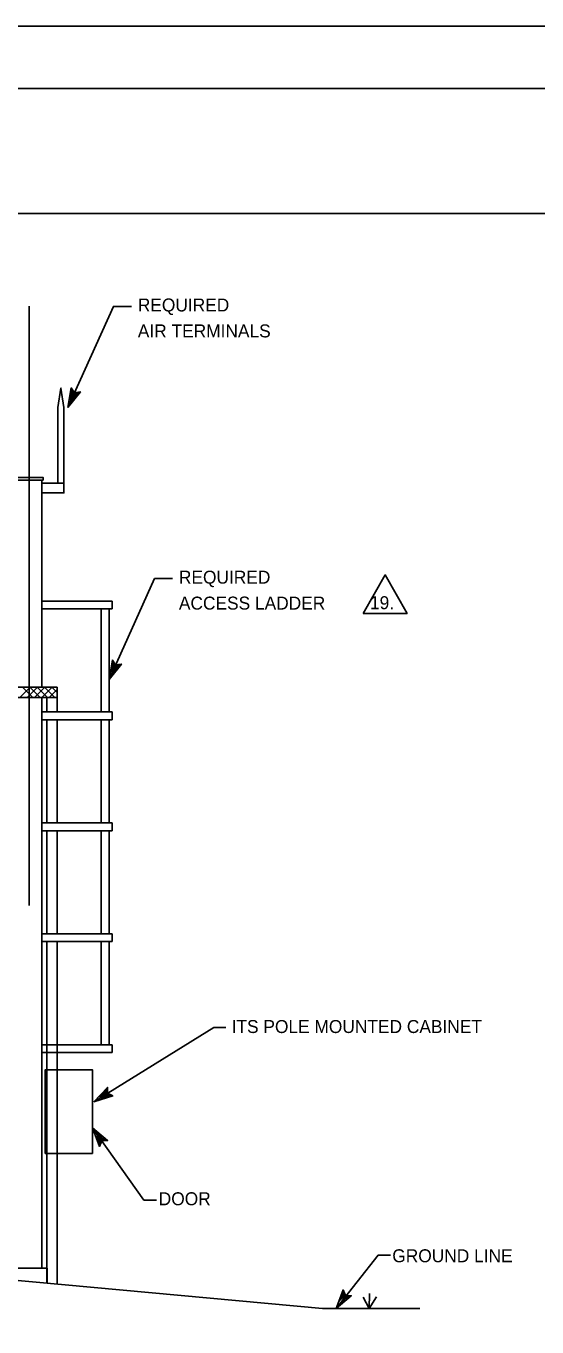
# Model space of a CAD drawing. Extents: x 515543 to 517243, y 661761 to 662861.
# Drawn here: x 516646 to 516850, y 662340 to 662861 of the extents above; entities that cross this region are included whole.
import ezdxf

# ---------------------------------------------------------------- set-up
doc = ezdxf.new("R2010")
doc.units = 0
for name, color, linetype in [('Level 40', 7, 'Continuous'), ('Level 62', 7, 'Continuous'), ('Level 8', 7, 'Continuous'), ('LTT', 7, 'Continuous'), ('SHT-BDR', 7, 'Continuous'), ('SHT-BNDRY', 7, 'Continuous')]:
    doc.layers.add(name, color=color, linetype=linetype)

msp = doc.modelspace()

# ---------------------------------------------------------------- linework, layer by layer
at = {"layer": 'Level 40'}
msp.add_lwpolyline([(516658.59, 662677.85), (516658.59, 662708.18), (516659.82, 662715.94), (516660.99, 662708.16), (516660.99, 662677.85)], dxfattribs=at)
msp.add_lwpolyline([(516652.24, 662677.85), (516660.99, 662677.85), (516660.99, 662674), (516652.24, 662674)], close=True, dxfattribs=at)
at = {"layer": 'Level 62'}
msp.add_lwpolyline([(515542.51, 661760.72), (517242.52, 661760.72), (517242.52, 662860.72), (515542.51, 662860.72)], close=True, dxfattribs=at)
at = {"layer": 'Level 8'}
for p, q in [((516647.05, 662508.97), (516647.05, 662748.72)), ((516641.35, 662679.08), (516652.75, 662679.08)), ((516652.23, 662596.32), (516652.23, 662679.08)), ((516652.23, 662630.77), (516680.28, 662630.77)), ((516680.28, 662630.77), (516680.28, 662627.66)), ((516652.23, 662627.66), (516680.28, 662627.66)), ((516675.95, 662627.66), (516675.95, 662586.4)), ((516679.06, 662627.66), (516679.06, 662586.4)), ((516571.16, 662596.32), (516658.3, 662596.32)), ((516571.16, 662592.24), (516658.3, 662592.24)), ((516643.42, 662592.24), (516647.5, 662596.32)), ((516644.49, 662596.32), (516648.57, 662592.24)), ((516646.35, 662592.24), (516650.43, 662596.32)), ((516647.42, 662596.32), (516651.51, 662592.24)), ((516649.28, 662592.24), (516653.37, 662596.32)), ((516650.35, 662596.32), (516654.44, 662592.24)), ((516652.22, 662592.24), (516656.3, 662596.32)), ((516652.23, 662363.97), (516652.23, 662592.24)), ((516653.29, 662596.32), (516657.37, 662592.24)), ((516654.15, 662592.24), (516654.15, 662586.4)), ((516655.15, 662592.24), (516658.3, 662595.39)), ((516656.22, 662596.32), (516658.3, 662594.25)), ((516658.08, 662592.24), (516658.3, 662592.45)), ((516658.3, 662596.32), (516658.3, 662586.4)), ((516652.23, 662586.4), (516680.28, 662586.4)), ((516680.28, 662586.4), (516680.28, 662583.29)), ((516652.23, 662583.29), (516680.28, 662583.29)), ((516654.15, 662583.29), (516654.15, 662542.04)), ((516658.3, 662583.29), (516658.3, 662542.04)), ((516675.95, 662583.29), (516675.95, 662542.04)), ((516679.06, 662583.29), (516679.06, 662542.04)), ((516652.23, 662542.04), (516680.28, 662542.04)), ((516680.28, 662542.04), (516680.28, 662538.93)), ((516680.28, 662542.04), (516680.28, 662538.93)), ((516652.23, 662538.93), (516680.28, 662538.93)), ((516654.15, 662538.93), (516654.15, 662497.68)), ((516658.3, 662538.93), (516658.3, 662497.68)), ((516675.95, 662538.93), (516675.95, 662497.68)), ((516679.06, 662538.93), (516679.06, 662497.68)), ((516652.23, 662497.68), (516680.28, 662497.68)), ((516652.23, 662494.57), (516680.28, 662494.57)), ((516654.15, 662494.57), (516654.15, 662453.32)), ((516658.3, 662494.57), (516658.3, 662453.32)), ((516675.95, 662494.57), (516675.95, 662453.32)), ((516679.06, 662494.57), (516679.06, 662453.32)), ((516680.28, 662497.68), (516680.28, 662494.57)), ((516680.28, 662497.68), (516680.28, 662494.57)), ((516652.23, 662453.32), (516680.28, 662453.32)), ((516654.15, 662453.32), (516654.15, 662358.02)), ((516658.3, 662453.32), (516658.3, 662357.64)), ((516680.28, 662453.32), (516680.28, 662450.21)), ((516680.28, 662453.32), (516680.28, 662450.21)), ((516652.23, 662450.21), (516680.28, 662450.21)), ((516639.79, 662363.97), (516654.31, 662363.97)), ((516654.31, 662358), (516654.31, 662363.97)), ((516783.15, 662347.89), (516780.7, 662352.44)), ((516783.15, 662347.89), (516783.21, 662353.91)), ((516783.15, 662347.89), (516786.01, 662352.57))]:
    msp.add_line(p, q, dxfattribs=at)
for points in [[(516688.07, 662748.61), (516680.85, 662748.61), (516662.63, 662708.23)], [(516641.35, 662679.08), (516641.35, 662680.12), (516652.75, 662680.12), (516652.75, 662679.08)], [(516704.51, 662639.76), (516697.29, 662639.76), (516679.06, 662599.37)], [(516673, 662430.56), (516720.94, 662460.2), (516725.8, 662460.2)], [(516698.01, 662391.19), (516692.99, 662391.19), (516672.42, 662420.07)], [(516791.71, 662369.13), (516786.69, 662369.13), (516769.91, 662347.89)], [(516580.14, 662364.81), (516764.49, 662347.89), (516803.44, 662347.89)]]:
    msp.add_lwpolyline(points, dxfattribs=at)
msp.add_lwpolyline([(516653.58, 662409.85), (516672.42, 662409.85), (516672.42, 662443.31), (516653.58, 662443.31)], close=True, dxfattribs=at)
at = {"layer": 'LTT'}
for points in [[(516663.96, 662716.02), (516662.63, 662708.23)], [(516667.59, 662714.38), (516662.63, 662708.23)], [(516665.21, 662713.95), (516663.18, 662711.12), (516664.77, 662714.63), (516663.69, 662713.75), (516664.23, 662714.94), (516663.96, 662716.02), (516665.26, 662714.07)], [(516665.21, 662713.95), (516664.43, 662710.55), (516666.01, 662714.07), (516666.07, 662712.68), (516666.61, 662713.87), (516667.59, 662714.38), (516665.26, 662714.07)], [(516680.4, 662607.17), (516679.06, 662599.37)], [(516681.65, 662605.1), (516679.62, 662602.26), (516681.2, 662605.78), (516680.13, 662604.9), (516680.66, 662606.09), (516680.4, 662607.17), (516681.7, 662605.21)], [(516684.03, 662605.53), (516679.06, 662599.37)], [(516681.65, 662605.1), (516680.87, 662601.7), (516682.45, 662605.22), (516682.51, 662603.83), (516683.04, 662605.02), (516684.03, 662605.53), (516681.7, 662605.21)], [(516678.46, 662436.28), (516673, 662430.56)], [(516678.34, 662433.87), (516675.07, 662432.65), (516678.35, 662434.68), (516676.97, 662434.55), (516678.08, 662435.24), (516678.46, 662436.28), (516678.45, 662433.93)], [(516680.55, 662432.89), (516673, 662430.56)], [(516678.34, 662433.87), (516675.79, 662431.48), (516679.07, 662433.51), (516678.34, 662432.33), (516679.45, 662433.02), (516680.55, 662432.89), (516678.45, 662433.93)], [(516678.48, 662414.99), (516672.42, 662420.07)], [(516675.24, 662412.68), (516672.42, 662420.07)], [(516676.07, 662414.95), (516673.52, 662417.34), (516675.76, 662414.2), (516674.53, 662414.85), (516675.29, 662413.79), (516675.24, 662412.68), (516676.14, 662414.85)], [(516676.07, 662414.95), (516674.64, 662418.13), (516676.88, 662414.99), (516676.66, 662416.37), (516677.42, 662415.3), (516678.48, 662414.99), (516676.14, 662414.85)], [(516772.73, 662355.28), (516769.91, 662347.89)], [(516775.97, 662352.97), (516769.91, 662347.89)], [(516773.55, 662353.01), (516771.01, 662350.62), (516773.25, 662353.76), (516772.02, 662353.11), (516772.78, 662354.17), (516772.73, 662355.28), (516773.62, 662353.11)], [(516773.55, 662353.01), (516772.12, 662349.82), (516774.36, 662352.96), (516774.15, 662351.59), (516774.91, 662352.65), (516775.97, 662352.97), (516773.62, 662353.11)]]:
    msp.add_lwpolyline(points, dxfattribs=at)
at = {"layer": 'SHT-BDR'}
msp.add_lwpolyline([(515667.5, 661835.77), (517167.5, 661835.77), (517167.5, 662785.77), (515667.5, 662785.77)], close=True, dxfattribs=at)
at = {"layer": 'SHT-BNDRY'}
for points in [[(515605.01, 661785.72), (517217.52, 661785.72), (517217.52, 662835.72), (515605.01, 662835.72)], [(516780.67, 662625.79), (516789.57, 662641.22), (516798.28, 662625.79)]]:
    msp.add_lwpolyline(points, close=True, dxfattribs=at)

# ---------------------------------------------------------------- texts
at = {"layer": 'Level 8'}
for s, p in [('REQUIRED', (516690.58, 662746.57)), ('AIR TERMINALS', (516690.58, 662736.2)), ('REQUIRED', (516707.02, 662637.72)), ('ACCESS LADDER', (516707.02, 662627.35)), ('19.', (516783.47, 662627.51)), ('ITS POLE MOUNTED CABINET', (516728.11, 662458.02)), ('DOOR', (516698.95, 662389.15))]:
    msp.add_text(s, height=5.184, rotation=360, dxfattribs=at).set_placement(p)
msp.add_text('GROUND LINE', height=5.184, dxfattribs=at).set_placement((516792.38, 662366.35))

doc.saveas('drawing.dxf')
